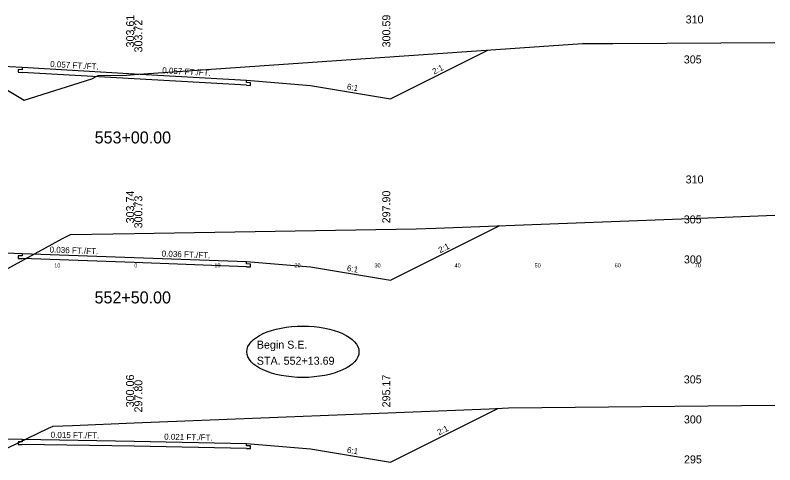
# Model space of a CAD drawing. Extents: x 1000 to 1162, y 999 to 8520.
# Drawn here: x 1065.1 to 1160, y 7344.8 to 7401 of the extents above; entities that cross this region are included whole.
import ezdxf

# ---------------------------------------------------------------- set-up
doc = ezdxf.new("R2010")
doc.units = 0
for name, color, linetype in [('Level 10', 7, 'Continuous'), ('Level 11', 7, 'Continuous'), ('Level 12', 7, 'Continuous'), ('Level 20', 7, 'Continuous'), ('Level 3', 7, 'Continuous'), ('Level 32', 7, 'Continuous'), ('Level 33', 7, 'Continuous'), ('Level 56', 7, 'Continuous'), ('Level 59', 7, 'Continuous'), ('Level 6', 7, 'Continuous'), ('Level 60', 7, 'Continuous'), ('Level 7', 7, 'Continuous')]:
    doc.layers.add(name, color=color, linetype=linetype)

msp = doc.modelspace()

# ---------------------------------------------------------------- linework, layer by layer
at = {"layer": 'Level 11'}
for p, q in [((1066, 7394.213), (1065.5, 7394.241)), ((1065.5, 7394.241), (1065.5, 7393.901)), ((1065.5, 7393.901), (1066, 7393.873)), ((1066, 7394.513), (1066, 7394.213)), ((1094, 7392.623), (1094, 7392.923)), ((1094.5, 7392.594), (1094, 7392.623)), ((1094, 7392.283), (1094.5, 7392.254)), ((1094.5, 7392.254), (1094.5, 7392.594)), ((1066, 7370.937), (1065.5, 7370.955)), ((1065.5, 7370.955), (1065.5, 7370.615)), ((1066, 7371.237), (1066, 7370.937)), ((1065.5, 7370.615), (1066, 7370.597)), ((1094, 7369.93), (1094, 7370.23)), ((1094.5, 7369.912), (1094, 7369.93)), ((1094, 7369.59), (1094.5, 7369.572)), ((1094.5, 7369.572), (1094.5, 7369.912)), ((1066, 7347.71), (1065.5, 7347.717)), ((1065.5, 7347.717), (1065.5, 7347.377)), ((1065.5, 7347.377), (1066, 7347.37)), ((1066, 7348.01), (1066, 7347.71)), ((1094, 7347.207), (1094, 7347.507)), ((1094.5, 7347.196), (1094, 7347.207)), ((1094.5, 7346.856), (1094.5, 7347.196)), ((1094, 7346.867), (1094.5, 7346.856))]:
    msp.add_line(p, q, dxfattribs=at)
at = {"layer": 'Level 12'}
for p, q in [((1080, 7393.078), (1066, 7393.873)), ((1094, 7392.283), (1080, 7393.078)), ((1080, 7370.094), (1066, 7370.597)), ((1094, 7369.59), (1080, 7370.094)), ((1080, 7347.158), (1066, 7347.37)), ((1094, 7346.867), (1080, 7347.158))]:
    msp.add_line(p, q, dxfattribs=at)
at = {"layer": 'Level 20'}
msp.add_ellipse((1101.06, 7358.954), major_axis=(7.001, 0), ratio=0.458988, dxfattribs=at)
at = {"layer": 'Level 59'}
for p, q in [((1066, 7394.513), (1080, 7393.718)), ((1080, 7393.718), (1094, 7392.923)), ((1066, 7371.237), (1080, 7370.734)), ((1080, 7370.734), (1094, 7370.23)), ((1066, 7348.01), (1080, 7347.798)), ((1080, 7347.798), (1094, 7347.507))]:
    msp.add_line(p, q, dxfattribs=at)
at = {"layer": 'Level 6'}
for p, q in [((1058, 7394.967), (1066, 7394.513)), ((1094, 7392.923), (1102, 7392.256)), ((1058, 7371.525), (1066, 7371.237)), ((1094, 7370.23), (1102, 7369.564)), ((1058, 7348.131), (1066, 7348.01)), ((1094, 7347.507), (1102, 7346.84))]:
    msp.add_line(p, q, dxfattribs=at)
at = {"layer": 'Level 60'}
for p, q in [((1080, 7393.611), (1135.987, 7397.484)), ((1135.987, 7397.484), (1139.767, 7397.502)), ((1139.767, 7397.502), (1160, 7397.626)), ((1066.263, 7390.421), (1074.682, 7393.068)), ((1074.682, 7393.068), (1075.49, 7393.504)), ((1075.49, 7393.504), (1079.016, 7393.543)), ((1079.016, 7393.543), (1080, 7393.611)), ((1062.791, 7392.481), (1066.263, 7390.421)), ((1117.674, 7374.42), (1152.722, 7375.755)), ((1152.722, 7375.755), (1160, 7376.029)), ((1072.048, 7373.609), (1080, 7373.741)), ((1080, 7373.741), (1115.226, 7374.323)), ((1115.226, 7374.323), (1117.674, 7374.42)), ((1062.27, 7368.325), (1071.039, 7373.119)), ((1071.039, 7373.119), (1072.048, 7373.609)), ((1124.314, 7351.811), (1126.757, 7351.94)), ((1126.757, 7351.94), (1160, 7352.279)), ((1080, 7350.062), (1124.314, 7351.811)), ((1072.278, 7349.758), (1080, 7350.062)), ((1059.811, 7344.824), (1069.274, 7349.419)), ((1069.274, 7349.419), (1069.881, 7349.648)), ((1069.881, 7349.648), (1072.278, 7349.758))]:
    msp.add_line(p, q, dxfattribs=at)
at = {"layer": 'Level 7'}
for p, q in [((1112, 7390.589), (1124.151, 7396.665)), ((1102, 7392.256), (1112, 7390.589)), ((1112, 7367.897), (1125.654, 7374.724)), ((1102, 7369.564), (1112, 7367.897)), ((1112, 7345.173), (1125.39, 7351.868)), ((1102, 7346.84), (1112, 7345.173))]:
    msp.add_line(p, q, dxfattribs=at)

# ---------------------------------------------------------------- texts
at = {"layer": 'Level 10'}
for s, p in [('303.61', (1079.986, 7397.001)), ('303.74', (1079.981, 7375.011)), ('300.06', (1079.968, 7352.017))]:
    msp.add_text(s, height=1, rotation=90, dxfattribs=at).set_placement(p)
at = {"layer": 'Level 11'}
for s, p in [(' 310', (1148.492, 7400)), (' 305', (1148.26, 7395)), (' 310', (1148.492, 7380)), (' 305', (1148.26, 7375)), (' 300', (1148.272, 7370)), (' 305', (1148.26, 7355)), (' 300', (1148.272, 7350)), (' 295', (1148.284, 7345))]:
    msp.add_text(s, height=1, dxfattribs=at).set_placement(p)
at = {"layer": 'Level 20'}
for s, p in [('Begin S.E.', (1095.307, 7359.338)), ('STA. 552+13.69', (1095.307, 7357.334))]:
    msp.add_text(s, height=1, dxfattribs=at).set_placement(p)
at = {"layer": 'Level 3'}
for s, p in [('553+00.00', (1075.051, 7385)), ('552+50.00', (1075.039, 7365))]:
    msp.add_text(s, height=1.5, dxfattribs=at).set_placement(p)
at = {"layer": 'Level 32'}
for s, rotation, p in [('0.057 FT./FT.', 356.74889, (1069.474, 7394.566)), ('2:1', 26.56505, (1117.457, 7393.597)), ('0.057 FT./FT.', 356.75008, (1083.474, 7393.771)), ('6:1', 350.53768, (1106.517, 7391.757)), ('0.036 FT./FT.', 357.93955, (1069.412, 7371.365)), ('2:1', 26.56505, (1118.208, 7371.281)), ('0.036 FT./FT.', 357.9418, (1083.412, 7370.861)), ('6:1', 350.53768, (1106.517, 7369.064)), ('2:1', 26.56505, (1118.076, 7348.491)), ('0.015 FT./FT.', 359.132, (1069.553, 7348.206)), ('0.021 FT./FT.', 358.80842, (1083.72, 7347.97)), ('6:1', 350.53768, (1106.517, 7346.341))]:
    msp.add_text(s, height=0.75, rotation=rotation, dxfattribs=at).set_placement(p)
at = {"layer": 'Level 33'}
for s, p in [('300.59', (1111.981, 7397.005)), ('297.90', (1111.977, 7375.01)), ('295.17', (1111.974, 7352.004))]:
    msp.add_text(s, height=1, rotation=90, dxfattribs=at).set_placement(p)
at = {"layer": 'Level 56'}
for s, p in [('10', (1070, 7369.5)), ('0', (1080, 7369.5)), ('10', (1090, 7369.5)), ('20', (1100, 7369.5)), ('30', (1110, 7369.5)), ('40', (1120, 7369.5)), ('50', (1130, 7369.5)), ('60', (1140, 7369.5)), ('70', (1150, 7369.5))]:
    msp.add_text(s, height=0.5, dxfattribs=at).set_placement(p)
at = {"layer": 'Level 59'}
for s, p in [(' 303.72', (1081.006, 7396.003)), (' 300.73', (1081.003, 7374.013)), (' 297.80', (1081.004, 7350.998))]:
    msp.add_text(s, height=1, rotation=90, dxfattribs=at).set_placement(p)

doc.saveas('drawing.dxf')
